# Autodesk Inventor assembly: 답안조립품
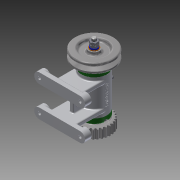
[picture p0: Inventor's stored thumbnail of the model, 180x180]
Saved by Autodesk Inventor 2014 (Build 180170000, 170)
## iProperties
Created: 2015-11
Part Number: 답안조립품
Document SubType Name: Assembly
Designer: user
Author: user
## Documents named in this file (16)
- C:\Users\user\Desktop\451110V1004\답안조립품.iam
- C:\Users\user\Desktop\451110V1004\축.ipt
- C:\Users\user\Desktop\451110V1004\베어링 15 x 32 x 9.ipt
- C:\Users\user\Desktop\451110V1004\본체.ipt
- C:\Users\user\Desktop\451110V1004\키 3 x 3 x 12.ipt
- C:\Users\user\Desktop\451110V1004\V벨트풀리.ipt
- C:\Users\user\Desktop\451110V1004\스퍼기어.ipt
- C:\Users\user\Desktop\451110V1004\와셔 6x11.5.ipt
- C:\Users\user\Desktop\451110V1004\스프링와셔 8.ipt
- C:\Users\user\Desktop\451110V1004\와셔 8x17.ipt
- C:\Users\user\Desktop\451110V1004\너트 M 8.ipt
- C:\Users\user\Desktop\451110V1004\커버.ipt
- C:\Users\user\Desktop\451110V1004\볼트 M4 x 12.ipt
- C:\Users\user\Desktop\451110V1004\오일 실 15 25 7.ipt
- C:\Users\user\Desktop\451110V1004\니플 M 6 x 0.75.ipt
- C:\Users\user\Desktop\451110V1004\볼트 M 6 x 8.ipt
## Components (11 placed, 3 different names)
1. KS B 2023 6002 - 15 x 32 x 9:3 — Insert:14, Insert:15
2. KS B 2023 6002 - 15 x 32 x 9:4 — Insert:13
3. V벨트풀리:1 — Insert:29, Angle:9
4. ISO 4762 M4 x 12:2 — Insert:19
5. ISO 4762 M4 x 12:3
6. ISO 4762 M4 x 12:4
7. ISO 4762 M4 x 12:5
8. ISO 4762 M4 x 12:1 — Insert:18
9. ISO 4762 M4 x 12:6
10. ISO 4762 M4 x 12:7
11. ISO 4762 M4 x 12:8
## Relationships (7: Insert 6, Angle 1)
- Insert:13: KS B 2023 6002 - 15 x 32 x 9:4
- Insert:14: KS B 2023 6002 - 15 x 32 x 9:3
- Insert:15: KS B 2023 6002 - 15 x 32 x 9:3
- Insert:18: ISO 4762 M4 x 12:1
- Insert:19: ISO 4762 M4 x 12:2
- Insert:29: V벨트풀리:1
- Angle:9: V벨트풀리:1
